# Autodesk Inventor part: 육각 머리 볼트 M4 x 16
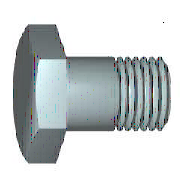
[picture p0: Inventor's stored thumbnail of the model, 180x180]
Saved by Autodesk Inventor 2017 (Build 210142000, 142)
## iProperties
IsCustomPart: 0
Created: 2012-02
Part Number: 육각 머리 볼트 M4 x 16
Material: 강철, 연강
Description: 6각 머리 볼트 및 6각 머리 나사
Document SubType Name: Modeling
Standard: KS B 1002
Designer: mduedu
Standards Organization: KS
Language: ko-KR
Size Designation: A + B M4 x 16
Categories: <MemberInstance><Categories><Category DisplayName="조임쇠" InternalName="e4da775c-781d-43d5-af7c-5136215cf5a6" Mnemonic="FSTN"><Category DisplayName="볼트" InternalN
Density: 7.86 g/cm^3
Mass: 2.45486 g
Surface Area: 3.4613 cm^2
Volume: 0.312323 cm^3
Appearance: 강철
Author: mduedu
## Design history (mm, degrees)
sketch "스케치1"
  geometry: L1 (0, 2.94)-(0, 2); L2 (2.1, 2)-(16, 2); L3 (16, 2)-(16, 0); L4 (16, 0)-(-0.4, 0); L5 (-3.68, 0)-(19.28, 0) reference; L6 (-0.4, 0)-(-0.4, 2.94); L7 (-0.4, 2.94)-(0, 2.94); L8 (2.1, 2)-(1.67, 2); L9 (1.67, 2)-(0, 2); L10 (0, -0.588)-(0, 3.528) reference
  constraints: 16 end point, 2 collinear, 2 perpendicular, 1 parallel
  dimensions: "d0" = 16 distance between parallel lines of L3 L1 (= NLG); "d1" = 13.9 distance from line of L2.start L3 (= GEL); "d2" = 4 diameter of L2 L4 (= GD); "d9" = 0.4001 distance between parallel lines of L6 L1 (computed from SD); "d10" = 5.88 diameter of L7 L4 (= SD2); "d13" = 0.42952 distance of L2.start L8.end (computed from GAL); "d14" = 4 diameter of L9 L4 (= BDM)
revolve "본체" sketch "스케치1" stored, may be unused: angle "d12" = 90 deg
sketch "스케치2"
  geometry: L1 (0, 4.041)-(3.5, 2.021); L2 (3.5, 2.021)-(3.5, -2.021); L3 (3.5, -2.021)-(0, -4.041); L4 (0, -4.041)-(-3.5, -2.021); L5 (-3.5, -2.021)-(-3.5, 2.021); L6 (-3.5, 2.021)-(0, 4.041); 2 further points
  constraints: 12 end point, 1 coincident, 1 vertical, 11 other
  dimensions: "d11" = 7 distance between parallel lines of L5 L2 (= SW)
extrude "머리" join sketch "스케치2" distance "d3" = 2.4 (= KOH - SD); taper "d4" = 0 deg
sketch "스케치4"
  geometry: L1 (-2.8, 3.5)-(-2.8, 4.041); L2 (-2.8, 4.041)-(-2.487, 4.041); L3 (-2.487, 4.041)-(-2.8, 3.5); L4 (-3.28, 0)-(0.08, 0) reference; L5 (-0.4, 4.041)-(-2.8, 4.041) reference; L6 (-2.8, 2.021)-(-2.8, 4.041) reference
  constraints: 6 end point, 2 collinear, 1 perpendicular, 1 vertical
  dimensions: "d5" = 30 deg angle of L3 L1 (= ANG1); "d19" = 7 diameter of L1.start L4 (= SW0)
revolve "모따기1" sketch "스케치4" stored, may be unused: angle "d21" = 90 deg
workplane "Work Plane1"
body "Solid1"
feature "스레드" dims "d15" = 13.9 (= GEL), "d16" = 0
chamfer "모따기2" distance "d6" = 0.42941 (= -0.5 x SPD + 0.5 x GD); stored, may be unused: second distance "d7" = 0.42952 (computed from GUL), angle "d55" = 45 deg
other parameters: "NLG" = 16 [user parameter; used in 1 equation term], "GD" = 4 (= NND) [user parameter; used in 2 equation terms], "BDM" = 4 (= NND) [user parameter; used in 1 equation term], "KOH" = 2.8 [user parameter; used in 1 equation term], "GEL" = 13.9 [user parameter; used in 2 equation terms], "SW" = 7 [user parameter; used in 3 equation terms], "SW0" = 7 (= SW) [user parameter; used in 1 equation term], "SPD" = 3.14117 (= NND - 1.2269 x PTC) [user parameter; used in 1 equation term], "SD2" = 5.88 (= SDH) [user parameter; used in 1 equation term], "SD" = 0.4 [user parameter; used in 2 equation terms], "ANG1" = 30 deg [user parameter; used in 1 equation term], "GAL" = 0.42941 (= 0.61345 x PTC) [user parameter; used in 1 equation term], "GUL" = 0.42941 (= 0.61345 x PTC) [user parameter; used in 1 equation term], "d8" = 0, "RR" = 0.2 [user parameter], "d57" = 0, "d58" = 0, "TPU" = 14.28571 (computed from PTC) [user parameter], "GD1" = 3.14117 (= THREADDIA - 1.2269 x PTC) [user parameter], "THREADDIA" = 4 [user parameter; used in 1 equation term], "SDH" = 5.88 [user parameter; used in 1 equation term], "SDHG" = 2.1 [user parameter], "TOA" = 30 deg [user parameter], "PTC" = 0.7 [user parameter; used in 5 equation terms], "NND" = 4 [user parameter; used in 3 equation terms], "E0" = 8.085 (= 1.155 x SW) [user parameter]
